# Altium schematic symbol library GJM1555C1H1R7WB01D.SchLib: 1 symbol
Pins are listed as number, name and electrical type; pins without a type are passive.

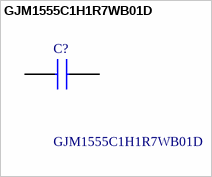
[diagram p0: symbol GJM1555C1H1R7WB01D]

## GJM1555C1H1R7WB01D
designator C?
Capacitor GJM15_0.10 L=1.0mm W=0.5mm T=0.5mm; Manufacturer_Name: Murata Electronics; Geometry.Height: 0.55mm
footprint CAPC1005X55N
pins: 1, 2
